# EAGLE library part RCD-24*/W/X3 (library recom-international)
Constant Current Output LED Driver Analogue Dimming and PWM Dimming ON/OFF Source: http://www.recom-international.de/pdf/Innoline/RCD-24.pdf
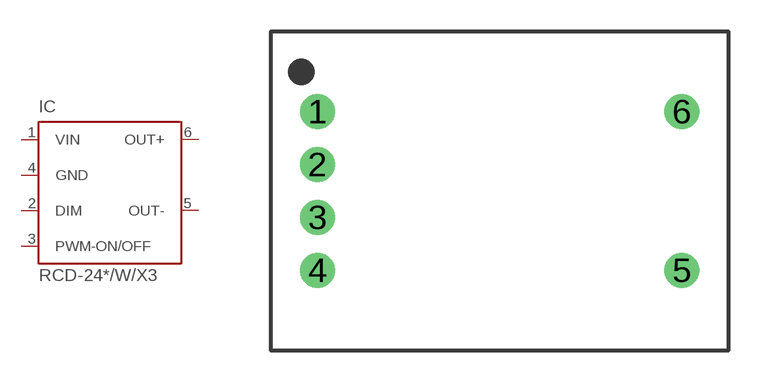
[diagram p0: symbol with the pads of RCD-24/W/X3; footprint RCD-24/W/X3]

Designator prefix IC

## RCD-24-0.30/W/X3 (OC_FARNELL: unknown; OC_NEWARK: unknown), RCD-24-0.35/W/X3 (OC_FARNELL: unknown; OC_NEWARK: unknown), RCD-24-0.50/W/X3 (OC_FARNELL: unknown; OC_NEWARK: unknown), RCD-24-0.60/W/X3 (OC_FARNELL: unknown; OC_NEWARK: unknown), RCD-24-0.70/W/X3 (OC_FARNELL: unknown; OC_NEWARK: unknown), RCD-24-1.00/W/X3 (OC_FARNELL: unknown; OC_NEWARK: unknown), RCD-24-1.20/W/X3 (OC_FARNELL: unknown; OC_NEWARK: unknown)  [RCD-24/W/X3]
1  VIN  in
2  DIM  pas
3  PWM-ON/OFF  pas
4  GND  pwr
5  OUT-  out
6  OUT+  out

## Footprint RCD-24/W/X3 (pad centres in mm)
DC/DC Converter RCD.24 Series /W/X3 Source: http://www.recom-international.com/pdf/Innoline-2008/RCD-24.pdf
drill 1 pad 1.676 round: 1 -8.75,3.81; 2 -8.75,1.27; 3 -8.75,-1.27; 4 -8.75,-3.81; 5 8.75,-3.81; 6 8.75,3.81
